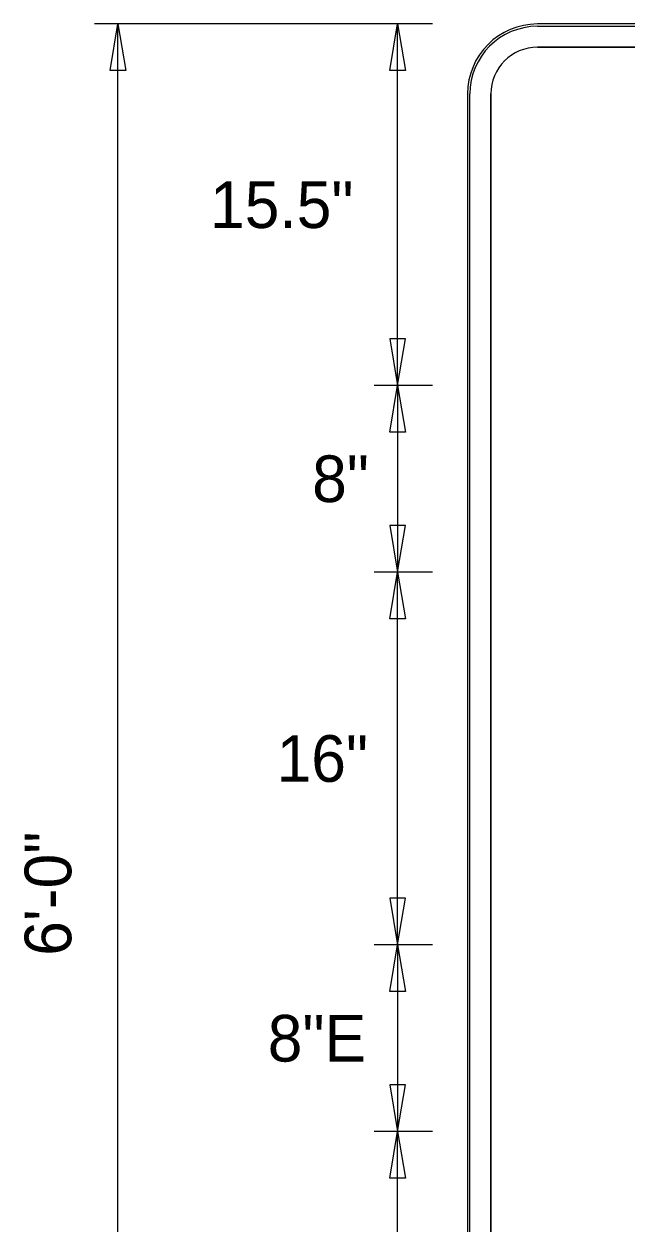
# Model space of a CAD drawing. Extents: x 1274.1 to 1363.1, y 833.5 to 890.6.
# Drawn here: x 1338.544 to 1340.697, y 881.658 to 885.942 of the extents above; entities that cross this region are included whole.
import ezdxf

# ---------------------------------------------------------------- set-up
doc = ezdxf.new("R2010")
doc.units = 0
for name, color, linetype in [('GSBWFill', 7, 'Continuous'), ('GSColorFill', 7, 'Continuous'), ('GSDims', 7, 'Continuous'), ('GSOutline', 7, 'Continuous')]:
    doc.layers.add(name, color=color, linetype=linetype)

msp = doc.modelspace()

# ---------------------------------------------------------------- linework, layer by layer
at = {"layer": 'GSBWFill'}
for p, q in [((1350.8803, 885.942), (1340.3803, 885.942)), ((1340.3803, 885.8586), (1350.8803, 885.8586)), ((1340.1303, 885.692), (1340.1303, 880.192)), ((1340.2136, 880.192), (1340.2136, 885.692))]:
    msp.add_line(p, q, dxfattribs=at)
for radius in [0.25, 0.1667]:
    msp.add_arc((1340.3803, 885.692), radius, 90, 180, dxfattribs=at)
at = {"layer": 'GSColorFill'}
for p, q in [((1350.8803, 885.942), (1340.3803, 885.942)), ((1350.8803, 885.942), (1340.3803, 885.942)), ((1350.8803, 885.942), (1340.3803, 885.942)), ((1340.3803, 885.9336), (1350.8803, 885.9336)), ((1340.3803, 885.8586), (1350.8803, 885.8586)), ((1340.1303, 885.692), (1340.1303, 880.192)), ((1340.1303, 885.692), (1340.1303, 880.192)), ((1340.1303, 885.692), (1340.1303, 880.192)), ((1340.1386, 880.192), (1340.1386, 885.692)), ((1340.2136, 880.192), (1340.2136, 885.692))]:
    msp.add_line(p, q, dxfattribs=at)
for radius in [0.25, 0.25, 0.25, 0.2417, 0.1667]:
    msp.add_arc((1340.3803, 885.692), radius, 90, 180, dxfattribs=at)
at = {"layer": 'GSDims'}
for p, q in [((1339.0053, 885.942), (1338.797, 885.942)), ((1338.8803, 879.942), (1338.8803, 885.942)), ((1340.0053, 885.942), (1339.0053, 885.942)), ((1340.0053, 885.942), (1339.797, 885.942)), ((1339.8803, 884.6505), (1339.8803, 885.942)), ((1340.0053, 884.6505), (1339.797, 884.6505)), ((1340.0053, 884.6505), (1339.797, 884.6505)), ((1339.8803, 884.6505), (1339.8803, 883.9838)), ((1340.0053, 883.9838), (1339.797, 883.9838)), ((1340.0053, 883.9838), (1339.797, 883.9838)), ((1339.8803, 882.6513), (1339.8803, 883.9838)), ((1340.0053, 882.6513), (1339.797, 882.6513)), ((1340.0053, 882.6513), (1339.797, 882.6513)), ((1339.8803, 882.6513), (1339.8803, 881.9846)), ((1340.0053, 881.9846), (1339.797, 881.9846)), ((1340.0053, 881.9846), (1339.797, 881.9846)), ((1339.8803, 879.942), (1339.8803, 881.9846))]:
    msp.add_line(p, q, dxfattribs=at)
for points in [[(1338.8803, 885.942), (1338.9081, 885.7753), (1338.8525, 885.7753)], [(1339.8803, 885.942), (1339.9081, 885.7753), (1339.8525, 885.7753)], [(1339.8803, 884.6505), (1339.9081, 884.8171), (1339.8525, 884.8171)], [(1339.8803, 884.6505), (1339.9081, 884.4838), (1339.8525, 884.4838)], [(1339.8803, 883.9838), (1339.9081, 884.1505), (1339.8525, 884.1505)], [(1339.8803, 883.9838), (1339.9081, 883.8171), (1339.8525, 883.8171)], [(1339.8803, 882.6513), (1339.9081, 882.818), (1339.8525, 882.818)], [(1339.8803, 882.6513), (1339.9081, 882.4846), (1339.8525, 882.4846)], [(1339.8803, 881.9846), (1339.9081, 882.1513), (1339.8525, 882.1513)], [(1339.8803, 881.9846), (1339.9081, 881.818), (1339.8525, 881.818)]]:
    msp.add_lwpolyline(points, close=True, dxfattribs=at)
at = {"layer": 'GSOutline'}
for p, q in [((1350.8803, 885.942), (1340.3803, 885.942)), ((1350.8803, 885.8586), (1340.3803, 885.8586)), ((1340.1303, 885.692), (1340.1303, 880.192)), ((1340.2136, 885.692), (1340.2136, 880.192))]:
    msp.add_line(p, q, dxfattribs=at)
for radius in [0.25, 0.1667]:
    msp.add_arc((1340.3803, 885.692), radius, 90, 180, dxfattribs=at)

# ---------------------------------------------------------------- texts
at = {"layer": 'GSDims'}
for s, p in [('15.5"', (1339.2097, 885.2129)), ('8"', (1339.5747, 884.2338)), ('16"', (1339.4477, 883.2342)), ('8"E', (1339.416, 882.2346))]:
    msp.add_text(s, height=0.16667, dxfattribs=at).set_placement(p)
msp.add_text('6\'-0"', height=0.16667, rotation=90, dxfattribs=at).set_placement((1338.7136, 882.6126))

doc.saveas('drawing.dxf')
